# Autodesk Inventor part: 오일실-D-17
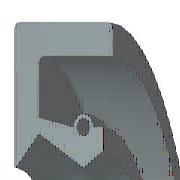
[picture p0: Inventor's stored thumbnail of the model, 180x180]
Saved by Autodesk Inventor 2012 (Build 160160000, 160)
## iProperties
IsCustomPart: 0
Company: 한국ATC센터
Created: 2014-12
Part Number: 오일실-D-17
Material: 고무
Description: 오일-실
Document SubType Name: Modeling
Standard: KS B 2804
Designer: KYOUNG IL JANG
Standards Organization: KS
Language: ko-KR
Size Designation: D - 17 30 8
Categories: <MemberInstance><Categories><Category DisplayName="샤프트 부품" InternalName="7f7aeb1f-a693-4053-b835-cee3144e0d98" Mnemonic="SHFT"><Category DisplayName="실링" Intern
Density: 0.93 g/cm^3
Mass: 2.05797 g
Surface Area: 29.3036 cm^2
Volume: 2.21288 cm^3
Author: KYOUNG IL JANG
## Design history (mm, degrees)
revolve "본체" stored, may be unused: angle "d17" = 90 deg
revolve "스프링1" stored, may be unused: angle "d18" = 90 deg
body "Solid1"
sketch "스케치1"
  geometry: L1 (0, 15)-(8, 15); L2 (8, 13.25)-(1.75, 13.25); L3 (1.75, 10.25)-(4.9, 8.5); L4 (4.9, 8.5)-(0, 8.5); L5 (0, 0)-(9.586, 0) reference; L6 (4.9, 8.5)-(6.3, 9.375); L7 (0, 18)-(0, -3) reference; L8 (-1.941, 0)-(11.507, 0) reference; L9 (4.2, 10.6)-(1.75, 11.21); L10 (1.75, 11.21)-(1.75, 13.25); L11 (0, 15)-(0, 8.588); L12 (4.9, 8.5)-(0, 8.5); L13 (1.75, 10.25)-(0.152, 8.528); L14 (8, 15)-(8, 13.25); L15 (5.6, 10.6)-(6.3, 10.6); L16 (6.3, 10.6)-(6.3, 9.375); C1 r 0.455 at (4.9, 10.6); A1 r 0.7 centre (4.9, 10.6) between (5.6, 10.6) and (4.2, 10.6); A2 r 0.088 centre (0.088, 8.588) between (0, 8.588) and (0.152, 8.528); 1 further point
  constraints: 28 end point, 5 horizontal alignment, 5 point on line, 4 point on circle, 4 vertical alignment, 3 centre point, 3 tangent, 2 collinear, 2 horizontal, 2 perpendicular, 1 coincident, 1 parallel
  dimensions: "d0" = 30 diameter of L1 L5 (= SD2); "d1" = 1.75 distance of L1.end L2.start (= SD); "d2" = 0.91 diameter of C1 (= SPDI); "d3" = 1.4 diameter of A1 (= SPDA); "d4" = 17 diameter of L3.end L5 (= NND); "d5" = 20.5 diameter of L3.start L5 (= TKDM); "d7" = 22.42 diameter of L9.end L5 (= TKDM + 0.24 x SWDT); "d8" = 1.75 distance between parallel lines of L11 L10 (= SD); "d9" = 4.9 distance from line of L11 C1.centre (= SPDST); "d10" = 21.2 diameter of C1.centre L5 (= HLDM); "d11" = 0.0875 radius of A2 (= 0.25 x LAB); "d12" = 6.3 distance between parallel lines of L11 L16 (= SDI); "d13" = 18.75 diameter of L6.end L5 (= ABDM); "d14" = 8 distance from line of L11 L1.end (= SWDT)
fillet "모깎기1" dims "d6" = 0.3 (= RR)
other parameters: "SD2" = 30 [user parameter; used in 1 equation term], "SWDT" = 8 [user parameter; used in 2 equation terms], "RR" = 0.3 [user parameter; used in 1 equation term], "SD" = 1.75 [user parameter; used in 2 equation terms], "NND" = 17 [user parameter; used in 1 equation term], "SPDA" = 1.4 [user parameter; used in 1 equation term], "SPDI" = 0.91 [user parameter; used in 1 equation term], "TKDM" = 20.5 [user parameter; used in 2 equation terms], "HLDM" = 21.2 [user parameter; used in 1 equation term], "ABDM" = 18.75 [user parameter; used in 1 equation term], "SDI" = 6.3 [user parameter; used in 1 equation term], "SPDST" = 4.9 [user parameter; used in 1 equation term], "LAB" = 0.35 [user parameter; used in 1 equation term], "d15" = 0, "d16" = 0, "d19" = 0
